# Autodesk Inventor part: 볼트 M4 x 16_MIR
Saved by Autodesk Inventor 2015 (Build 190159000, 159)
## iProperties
Created: 2025-08
Part Number: 볼트 M4 x 16_MIR
Material: 일반
Document SubType Name: Modeling
Designer: USER
Density: 1 g/cm^3
Appearance: 기본값
Author: USER
Author: jhkim
Description: 6각 소켓 머리 캡 나사
Creation Date: 2025-08-05
Sending System: Autodesk Inventor 2026
Preprocessor: ST-DEVELOPER v20.1
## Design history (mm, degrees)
derived "볼트 M4 x 16.ipt"
feature "Solid1::볼트 M4 x 16.ipt" dims "d0" = 10
tag "피쳐 태그1"
node "솔리드1"
